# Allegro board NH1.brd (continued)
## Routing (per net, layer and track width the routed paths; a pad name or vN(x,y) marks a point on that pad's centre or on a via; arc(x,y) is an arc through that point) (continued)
DDI0_HDMI_SDA_ALS: length 22.3
  IN1 w0.381: v1(13.51,88.04) 15,89.53 21.32,89.53 21.93,88.91 21.93,86.07 23.86,84.14 25.73,84.14 26.78,83.09 v1(26.78,82.12)
  BOTTOM w0.102: R56.1 26.7,82.21 v1(26.78,82.12)
  BOTTOM w0.457: v1(13.51,88.04) 13.75,88.28 J1HDMI1.16
DDI0_HPD_N: length 68.1
  TOP w0.102: v1(8.75,53.47) 8.43,53.16 U1.E14
  IN1 w0.102: v1(8.75,53.47) 8.75,53.62 9.09,53.96 9.09,54.99 8.94,55.14 8.41,55.14 8.33,55.06 4.69,55.06 3.41,56.34 2.7,56.34 1.89,57.16 1.89,69.83 2.4,70.34 2.4,73.07 1.97,73.49 1.97,80.21 8.08,86.31 18.3,86.31 19.39,85.22 20.61,85.22 v1(20.99,84.84)
  BOTTOM w0.102: v1(20.99,84.84) 21.01,84.86 22.85,84.86 R1HDMI3.1 24.5,84.03 25.16,84.03 25.38,84.26 29.46,84.26 29.6,84.4 29.6,85.7 29.92,86.02 Q1HDMI2.3
DDI0_PLLOBS_DN: length 1.2
  TOP w0.102: v1(18.7,46.18) 19.03,46.51 U1.AA4
  BOTTOM w0.102: v1(18.7,46.18) 18.99,46.47 R1AS26.1
DDI0_PLLOBS_DP: length 1.2
  TOP w0.089: U1.AA3 v1(18.7,45.53)
  BOTTOM w0.102: R1AS26.2 18.86,45.69 v1(18.7,45.53)
DDI0_TX0_DN: length 56.2
  TOP w0.089: U1.AB3 v1(20.05,45.53)
  IN1 w0.117: v1(20.05,45.53) 20.12,45.6 20.57,45.6 21.07,45.1 21.48,45.1 21.93,45.55 22.29,45.55 22.69,45.15 23.15,45.15 23.71,45.71 24.01,45.71 24.47,45.25 25.18,45.25 25.71,45.78 25.71,46.51 25.97,46.78 26.64,46.78 27.66,47.79 27.66,48.25 27.47,48.44 27.47,48.68 27.61,48.82 29.14,48.82 29.55,49.22 29.55,49.79 29.22,50.12 28.85,50.12 28.68,50.29 28.68,50.53 28.85,50.7 29.22,50.7 29.55,51.03 29.55,51.5 29.22,51.82 28.85,51.82 28.68,52 28.68,52.24 28.85,52.41 29.22,52.41 29.55,52.74 29.55,52.99 29.55,53.22 30.14,53.81 30.14,60.54 28.13,62.56 28.13,63.2 28.13,65.61 28.53,66.02 28.53,68.58 28.21,68.91 27.96,68.91 27.79,69.08 27.79,69.32 27.96,69.49 28.21,69.49 28.53,69.82 28.53,71.18 28.19,71.52 27.91,71.52 27.81,71.62 27.81,72.45 27.95,72.58 28.82,72.58 29.12,72.88 29.12,73.79 28.9,74.01 28.41,74.01 28.22,74.2 28.22,74.43 28.36,74.56 28.93,74.56 29.17,74.81 29.17,75.38 28.75,75.8 28.37,76.18 28.37,76.68 28.75,77.06 28.75,77.53 28.37,77.91 28.37,78.26 28.81,78.71 28.81,79.18 28.51,79.48 28.2,79.48 27.93,79.75 27.93,79.89 28.11,80.06 v1(28.89,80.06)
  BOTTOM w0.131: C1HDMI8.2 29.42,81.38 29.42,80.6 v1(28.89,80.06)
DDI0_TX0_DP: length 56.2
  TOP w0.102: U1.AB4 19.72,46.5 v1(20.05,46.18)
  IN1 w0.117: v1(20.05,46.18) 20.05,46.03 20.21,45.87 20.68,45.87 21.18,45.37 21.36,45.37 21.81,45.82 22.4,45.82 22.8,45.42 23.04,45.42 23.6,45.98 24.12,45.98 24.58,45.52 25.07,45.52 25.44,45.89 25.44,46.62 25.86,47.05 26.53,47.05 27.39,47.9 27.39,48.14 27.2,48.33 27.2,48.79 27.5,49.09 29.03,49.09 29.28,49.34 29.28,49.68 29.1,49.85 28.74,49.85 28.41,50.18 28.41,50.64 28.74,50.97 29.1,50.97 29.28,51.14 29.28,51.38 29.1,51.56 28.74,51.56 28.41,51.88 28.41,52.35 28.74,52.68 29.1,52.68 29.28,52.85 29.28,53.1 29.28,53.11 29.28,53.33 29.87,53.93 29.87,60.43 27.86,62.44 27.86,63.31 27.86,65.72 28.27,66.13 28.27,68.47 28.09,68.64 27.85,68.64 27.52,68.97 27.52,69.43 27.85,69.76 28.09,69.76 28.27,69.93 28.27,71.06 28.08,71.25 27.8,71.25 27.54,71.51 27.54,72.56 27.84,72.85 28.71,72.85 28.85,72.99 28.85,73.68 28.79,73.74 28.3,73.74 27.95,74.09 27.95,74.54 28.24,74.83 28.81,74.83 28.9,74.92 28.9,75.27 28.48,75.69 28.1,76.07 28.1,76.79 28.48,77.17 28.48,77.41 28.1,77.79 28.1,78.38 28.54,78.82 28.54,79.07 28.4,79.21 28.08,79.21 27.66,79.64 27.66,80 28,80.33 28.57,80.33 v1(28.89,80.66)
  BOTTOM w0.131: C1HDMI7.2 29.02,81.63 29.14,81.51 29.14,80.72 29.08,80.66 v1(28.89,80.66)
DDI0_TX1_DN: length 57.1
  TOP w0.102: U1.AA1 19.08,44.56 v1(19.4,44.23)
  TOP w0.131: v1(30.26,83.01) 30.34,83.09 31.2,83.09 31.53,83.42 31.53,83.64 C1HDMI6.2
  IN1 w0.102: 20.31,44.49 20.29,44.49 20.28,44.5 20.2,44.5 20.19,44.51 19.87,44.51 19.76,44.39 19.56,44.39 v1(19.4,44.23)
  IN1 w0.117: 20.31,44.49 20.5,44.49 20.67,44.32 20.67,44.01 21,43.68 21.46,43.68 21.61,43.82 21.79,44.01 21.79,44.32 21.96,44.49 22.26,44.49 22.64,44.12 23.2,44.12 23.58,44.49 23.77,44.49 23.93,44.34 23.93,43.88 24.19,43.62 24.81,43.62 25.2,44.01 25.2,44.32 25.38,44.49 26.08,44.49 26.42,44.83 26.42,45.4 26.66,45.64 27.23,45.64 27.63,46.04 27.63,46.61 27.87,46.85 28.44,46.85 28.84,47.25 28.84,47.82 29.08,48.06 29.65,48.06 30.31,48.72 30.31,49.22 30.31,52.9 30.91,53.5 30.91,60.86 28.89,62.87 28.89,63.08 29.25,63.44 29.25,63.85 28.89,64.2 28.89,64.43 29.06,64.6 29.51,64.6 29.88,64.97 29.88,66.02 29.3,66.6 29.3,70.39 30.28,71.37 30.28,75.35 29.52,76.12 29.52,78.33 29.98,78.78 29.98,80.54 29.56,80.96 29.56,82.65 30,83.09 30.19,83.09 v1(30.26,83.01)
DDI0_TX1_DP: length 57.1
  TOP w0.102: v1(19.4,44.88) 19.64,44.88 19.72,44.96 U1.AB2
  TOP w0.131: C1HDMI5.2 31.08,83.92 31.25,83.75 31.25,83.53 31.08,83.37 30.43,83.37 v1(30.26,83.54)
  IN1 w0.102: 20.31,44.76 20.2,44.76 20.2,44.76 19.77,44.76 19.65,44.64 19.48,44.64 19.4,44.72 v1(19.4,44.88)
  IN1 w0.117: v1(30.26,83.54) 30.08,83.36 29.89,83.36 29.29,82.76 29.29,80.85 29.71,80.42 29.71,78.9 29.25,78.44 29.25,76 30.01,75.24 30.01,71.48 29.03,70.5 29.03,66.49 29.61,65.91 29.61,65.08 29.4,64.87 28.95,64.87 28.62,64.54 28.62,64.09 28.98,63.73 28.98,63.55 28.62,63.19 28.62,62.76 30.64,60.75 30.64,53.61 30.04,53.01 30.04,52.79 30.04,52.79 30.04,48.83 29.53,48.33 28.97,48.33 28.57,47.93 28.57,47.36 28.33,47.12 27.76,47.12 27.36,46.72 27.36,46.15 27.12,45.91 26.55,45.91 26.15,45.51 26.15,44.94 25.97,44.76 25.26,44.76 24.94,44.43 24.94,44.12 24.7,43.89 24.3,43.89 24.2,43.99 24.2,44.45 23.89,44.76 23.47,44.76 23.09,44.39 22.75,44.39 22.38,44.76 21.85,44.76 21.52,44.43 21.52,44.12 21.35,43.95 21.11,43.95 20.94,44.12 20.94,44.43 20.61,44.76 20.31,44.76
DDI0_TX2_DN: length 59.7
  TOP w0.089: U1.Y1 18.38,44.55 v1(18.06,44.23)
  TOP w0.131: C1HDMI4.2 31.48,86.56 31.62,86.56 v1(31.77,86.71)
  IN1 w0.102: v1(18.06,44.23) 18.19,44.23 19.11,43.32 19.11,43.3 19.12,43.29
  IN1 w0.117: 19.12,43.29 19.55,42.87 21.73,42.87 22.22,43.35 22.62,43.35 23.25,42.71 25.39,42.71 31.08,48.41 31.08,52.58 31.67,53.18 31.67,61.2 30.07,62.8 30.07,64.08 30.65,64.65 30.65,66.34 30.07,66.91 30.07,70.07 31.05,71.05 31.05,75.67 30.29,76.43 30.29,78.01 30.74,78.47 30.74,80.85 30.32,81.28 30.32,82.06 31.46,83.19 31.46,84.19 32.43,85.16 32.43,86.36 32.17,86.62 31.86,86.62 v1(31.77,86.71)
DDI0_TX2_DP: length 59.7
  TOP w0.089: v1(18.06,44.88) 18.38,45.2 U1.Y2
  TOP w0.131: C1HDMI3.2 31.18,86.15 31.31,86.27 31.66,86.27 31.77,86.17 v1(31.77,86.02)
  IN1 w0.102: 19.31,43.48 19.3,43.49 19.29,43.49 18.06,44.72 v1(18.06,44.88)
  IN1 w0.117: 19.31,43.48 19.66,43.13 21.62,43.13 22.11,43.62 22.73,43.62 23.36,42.98 25.28,42.98 30.81,48.52 30.81,52.7 31.4,53.29 31.4,61.09 29.8,62.69 29.8,64.19 30.38,64.76 30.38,66.22 29.8,66.8 29.8,70.18 30.78,71.16 30.78,75.56 30.02,76.32 30.02,78.12 30.48,78.58 30.48,80.74 30.05,81.16 30.05,82.17 31.19,83.3 31.19,84.31 32.16,85.27 32.16,86.25 32.06,86.35 31.89,86.35 31.77,86.23 v1(31.77,86.02)
DDI0_TX3_DN: length 67.7
  TOP w0.089: U1.Y3 18.38,45.85 v1(18.06,45.53)
  TOP w0.131: C1HDMI2.2 31.49,88.72 31.78,88.72 v1(31.83,88.76)
  IN1 w0.102: 22.77,46.59 22.73,46.59 22.58,46.74 20.32,46.74 20.29,46.77 18.94,46.77 18.63,47.08 17.41,47.08 16.85,46.53 16.85,45.86 17.18,45.53 v1(18.06,45.53)
  IN1 w0.117: v1(31.83,88.76) 31.73,88.67 30.99,88.67 30.59,88.26 30.59,87.64 30.42,87.47 30.17,87.47 30,87.64 30,88.26 29.67,88.59 29.11,88.59 28.61,88.09 28.61,86.45 28.94,86.12 30.51,86.12 30.68,85.95 30.68,85.71 30.51,85.54 28.94,85.54 28.61,85.21 28.61,84.18 27.78,83.35 27.78,81.98 26.82,81.02 26.82,68.46 27.4,67.87 27.4,66.85 27.22,66.66 27.22,63.52 27.22,62.12 29.23,60.1 29.23,54.21 27.56,52.54 27.56,50.62 26.08,49.14 26.08,48.6 26.49,48.19 26.49,47.95 26.31,47.78 26.07,47.78 25.49,48.36 25.03,48.36 24.58,47.91 24.58,47.44 24.85,47.17 24.85,46.92 24.68,46.75 24.44,46.75 24.16,47.03 23.7,47.03 23.26,46.59 22.77,46.59
DDI0_TX3_DP: length 67.6
  TOP w0.089: v1(18.06,46.18) 18.38,46.5 U1.Y4
  TOP w0.131: C1HDMI1.2 31.2,88.31 31.32,88.43 31.64,88.43 31.83,88.24 v1(31.83,88.19)
  IN1 w0.102: 22.77,46.32 22.64,46.32 22.47,46.49 20.21,46.49 20.19,46.51 18.84,46.51 18.52,46.83 17.51,46.83 17.11,46.42 17.11,45.97 17.29,45.79 17.85,45.79 18.06,46 v1(18.06,46.18)
  IN1 w0.117: v1(31.83,88.19) 31.83,88.27 31.7,88.4 31.11,88.4 30.86,88.15 30.86,87.53 30.53,87.2 30.06,87.2 29.73,87.53 29.73,88.15 29.56,88.32 29.22,88.32 28.88,87.98 28.88,86.56 29.05,86.39 30.62,86.39 30.95,86.06 30.95,85.59 30.62,85.27 29.05,85.27 28.88,85.1 28.88,84.07 28.05,83.24 28.05,81.87 27.09,80.9 27.09,68.57 27.67,67.99 27.67,66.74 27.49,66.55 27.49,63.41 27.49,62.23 29.5,60.22 29.5,54.1 27.83,52.43 27.83,50.51 26.35,49.03 26.35,48.71 26.76,48.31 26.76,47.84 26.43,47.51 25.96,47.51 25.38,48.09 25.14,48.09 24.85,47.79 24.85,47.55 25.12,47.28 25.12,46.81 24.79,46.48 24.32,46.48 24.05,46.76 23.81,46.76 23.38,46.32 22.77,46.32
DDR3_DRAM_PWROK: length 74.1
  TOP w0.102: v1(10.17,29.85) 10.05,29.73 U1AP1.11 ; R1AS12.2 25.89,56.62 25.37,56.62 25.09,56.34 23.37,56.34 22.86,56.86 v1(22.77,56.86) 22.42,56.86 22.39,56.82 20.74,56.82 20.45,57.11 U1.AC20
  IN1 w0.102: v1(28.97,24.01) 28.81,24.16 28.81,28.76 27.24,30.33 17.06,30.33 16.18,29.45 16.18,26.33 15.89,26.04 13.73,26.04 13.29,26.47 13.29,28.04 11.74,29.6 10.42,29.6 v1(10.17,29.85)
  IN2 w0.102: v1(22.77,56.86) 24.3,55.33 25.82,55.33 26.41,54.73 26.41,54.73 28.71,52.43 28.71,41.15 29.42,40.44 29.42,24.47 v1(28.97,24.01)
DDR3_SOC_CMDPU: length 3.6
  TOP w0.254: R1AS64.2 22.89,58.77 21.89,57.78 U1.AE21
DDR3_SOC_DQTPU: length 3.3
  TOP w0.254: U1.AE20 22.19,57.11 22.6,57.52 R1AS73.2
DDR3_SOC_ODTPU: length 6.7
  TOP w0.254: R1AS63.2 25.54,61.91 25.54,61.2 25.03,60.69 24.51,60.69 24.12,60.29 24.12,59.93 23.42,59.23 22.84,59.23 22.06,58.45 U1.AE22
DDR3_VCCA_PWROK: length 73
  TOP w0.102: v2(25.14,55.94) 24.95,55.75 R1AS36.2 24.1,55.33 22.94,56.48 22.54,56.48 22.4,56.62 20.65,56.62 20.49,56.78 20.05,56.78 U1.AB20 ; v1(10.17,29.19) 10.03,29.33 U1AP1.12
  IN1 w0.102: v1(10.17,29.19) 10.4,29.42 11.66,29.42 13.12,27.97 13.12,26.4 13.65,25.86 15.96,25.86 16.36,26.26 16.36,29.38 17.13,30.15 27.17,30.15 28.64,28.68 28.64,23.7 v1(28.86,23.47)
  IN2 w0.102: v1(28.86,23.47) 28.94,23.47 29.42,23.96 29.42,24.18 29.63,24.38 29.63,40.54 28.92,41.25 28.92,52.51 28.76,52.67 28.76,52.67 25.5,55.94 v2(25.14,55.94)
DDR3_VREF: length 8.9
  TOP w0.165: 22.63,58.01 22.06,57.43 21.45,57.43 21.12,57.11 U1.AD20
  TOP w0.254: 22.63,58.01 22.77,58.15 27.13,58.15 R1AS77.1 C1AS71.2 R1AS76.2
DDR3L_ZQ_L8_A: length 4
  TOP w0.14: v1(2.96,75.96) 3.85,75.96 4.26,76.36 U1AM1.L8
  BOTTOM w0.102: R1AM1.1 2.96,76.06 v1(2.96,75.96)
DDR3L_ZQ_L8_B: length 3.5
  BOTTOM w0.14: R1AM2.1 12.37,75.95 9.94,75.95 9.52,76.37 9.31,76.37 U1AM2.L8
DDR3L_ZQ_L8_C: length 6.2
  TOP w0.102: U1AM3.L8 19.55,76.36
  TOP w0.14: v1(17.71,75.04) 17.71,75.74 18.04,76.06 18.47,76.06 18.52,76.01 19.19,76.01 19.55,76.36
  BOTTOM w0.102: v1(17.71,75.04) 17.71,75.65 16.3,77.06 R1AM3.1
DDR3L_ZQ_L8_D: length 4.2
  BOTTOM w0.102: U1AM4.L8 24.81,76.36 25.2,75.98
  BOTTOM w0.14: R1AM4.1 27.64,76.56 26.23,76.56 25.65,75.98 25.2,75.98
DLD01: length 4.8
  TOP w0.203: 10.17,24.67 10.55,25.05 U1AP1.21
  TOP w0.381: 10.17,24.67 9.19,24.67 8.75,24.23 8.75,23.82 7.91,22.98 C1AP24.1
DLDO4: length 1.8
  TOP w0.203: U1AP1.17 v1(8.24,27.33)
  BOTTOM w0.457: C1AP27.1 7.75,27.33 v1(8.24,27.33)
ELDO2: length 4.6
  TOP w0.203: U1AP1.2 8.72,33.33 8.37,33.69 8.37,34.09 8.32,34.13
  TOP w0.381: 8.32,34.13 8.32,34.7 7.9,35.13 7.9,35.14 6.64,36.4 C1AP29.1
EMMC_CLK: length 13.1
  TOP w0.102: v1(22,48.84) 21.68,49.16 U1.AE8
  IN1 w0.102: v1(22,48.84) 22.15,48.84 24.6,51.28 24.6,51.62 25.34,52.36 26.19,52.36 27.27,53.45 27.27,56.42 26.73,56.96 v1(26.73,57.66)
  BOTTOM w0.14: v1(26.73,57.66) 26.66,57.66 26.18,58.14 U1EMMC1.M6
EMMC_CMD: length 14.9
  TOP w0.102: U1.AB8 19.73,49.16 v1(20.05,48.84)
  IN1 w0.102: v1(20.05,48.84) 20.38,49.17 20.38,50.03 20.37,50.04 20.37,50.31 20.56,50.51 20.57,50.51 20.87,50.81 22.14,50.81 22.96,51.62 23.29,51.62 23.63,51.96 23.63,52.32 24.69,53.37 24.69,57.82 25.04,58.17 25.6,58.17 v1(26.16,57.61)
  BOTTOM w0.14: U1EMMC1.M5 25.63,58.14 v1(26.16,57.61)
EMMC_DATA_0: length 9.6
  TOP w0.102: v1(20.05,48.18) 19.73,48.5 U1.AB7
  IN1 w0.102: v1(25.29,51.42) 25.5,51.21 25.5,50.55 25.13,50.18 24.85,50.18 22.68,48 22.64,48 22.64,48 22.53,48 22.38,47.85 20.38,47.85 v1(20.05,48.18)
  BOTTOM w0.102: U1EMMC1.A3 24.62,52.09 v1(25.29,51.42)
EMMC_DATA_1: length 8.5
  TOP w0.102: v1(20.7,48.18) 20.38,48.5 U1.AC7
  IN1 w0.102: v1(20.7,48.18) 20.77,48.25 22.49,48.25 24.95,50.7 v1(25.14,50.7)
  BOTTOM w0.102: U1EMMC1.A4 25.12,52.38 25.11,52.37 25.11,52.15 25.69,51.57 25.69,51.52
  BOTTOM w0.14: v1(25.14,50.7) 25.4,50.7 25.64,50.95 25.64,51.23 25.69,51.28 25.69,51.52
EMMC_DATA_2: length 9.1
  TOP w0.102: v1(20.7,48.84) 20.38,49.16 U1.AC8
  IN1 w0.102: v1(26.35,51.67) 26.27,51.75 25.16,51.75 24.9,51.49 24.9,51.16 22.89,49.15 22.88,49.15 22.23,48.51 21.16,48.51 20.83,48.84 v1(20.7,48.84)
  BOTTOM w0.102: U1EMMC1.A5 25.62,52.42 26.35,51.69 v1(26.35,51.67)
EMMC_DATA_3: length 6.8
  TOP w0.102: U1.AB9 v1(20.05,49.48)
  IN1 w0.102: v1(20.05,49.48) 20.05,49.77 20.05,49.77 20.05,50.4 20.74,51.08 21.78,51.08 v1(22.77,52.08)
  BOTTOM w0.076: 23.2,52.89 23.87,52.89 U1EMMC1.B2
  BOTTOM w0.089: 22.77,52.43 22.77,52.46 23.2,52.89
  BOTTOM w0.14: 22.77,52.43 v1(22.77,52.08)
EMMC_DATA_4: length 8.1
  TOP w0.102: v1(19.4,49.48) 19.07,49.8 U1.AA9
  IN1 w0.102: v1(19.4,49.48) 19.8,49.88 19.8,50.55 20.6,51.35 21.58,51.35 22.63,52.41 23,52.41 v1(23.3,52.1)
  BOTTOM w0.076: U1EMMC1.B3 24.37,52.89 24.37,52.49
  BOTTOM w0.089: 24.37,52.49 23.99,52.1 v1(23.3,52.1)
EMMC_DATA_5: length 12.4
  TOP w0.102: v1(18.75,48.83) 18.75,48.83 U1.AA8
  IN1 w0.102: v1(18.75,48.83) 19.97,47.6 22.49,47.6 22.63,47.74 22.74,47.74 22.75,47.75 22.85,47.75 24.98,49.88 25.25,49.88 26.06,50.68 v1(26.06,51.11)
  BOTTOM w0.076: U1EMMC1.B4 25.38,52.89 25.38,52.26
  BOTTOM w0.089: 25.38,52.26 26,51.64 26,51.17 v1(26.06,51.11)
EMMC_DATA_6: length 15.7
  TOP w0.102: U1.Y8 v1(18.1,49.48)
  IN1 w0.102: v1(27.07,51.62) 27.07,51.17 26.67,50.76 26.67,50.43 25.51,49.27 25.23,49.27 23.06,47.09 19.76,47.09 19.01,47.84 18.57,47.84 18.1,48.32 v1(18.1,49.48)
  BOTTOM w0.076: U1EMMC1.B5 25.88,52.89 25.88,52.5
  BOTTOM w0.089: v1(27.07,51.62) 26.98,51.62 26.38,52.23 26.15,52.23 25.88,52.5
EMMC_DATA_7: length 13.3
  TOP w0.102: U1.Y7 18.42,48.46 v1(18.7,48.18)
  IN1 w0.102: v1(27.01,52.15) 26.93,52.15 26.73,51.95 26.73,51.26 26.36,50.89 26.36,50.55 25.38,49.57 25.11,49.57 22.93,47.39 22.64,47.39 22.59,47.34 19.87,47.34 19.03,48.18 v1(18.7,48.18)
  BOTTOM w0.076: U1EMMC1.B6 26.38,52.89 26.73,52.89 26.87,52.74 26.87,52.29
  BOTTOM w0.089: 26.87,52.29 v1(27.01,52.15)
EMMC_RESET: length 13.3
  TOP w0.102: v1(21.35,48.84) 21.03,49.16 U1.AD8
  IN1 w0.102: v1(21.35,48.84) 21.47,48.84 24.11,51.48 24.11,52.12 24.85,52.85 25.89,52.85 26.79,53.75 26.79,56.22 v1(25.4,57.61)
  BOTTOM w0.102: U1EMMC1.K5 25.62,57.38 v1(25.4,57.61)
GPIO_RCOMP: length 2.3
  TOP w0.254: R1AS49.1 4.07,46.92 4.33,46.66 4.34,46.66 4.6,46.41 5.48,46.41 5.58,46.51 U1.A4
HDA_RCOMP: length 3.8
  TOP w0.203: R1AS45.1 24.33,51.97 23.16,53.15 U1.AE14
HDMI_POWER_DN: length 2
  TOP w0.102: 28.29,89.21 v1(28.54,89.46)
  TOP w0.117: EU1HDMI1.12 28.29,89.21
  BOTTOM w0.102: v1(28.54,89.46) 28.1,89.9 R1HDMI1.2
HOLD_N_FLASH: length 5
  TOP w0.102: R1SPI4.1 27.93,51.5 27.93,51.94 28.59,52.61 29.53,52.61 29.84,52.29 EU1SPI1.7
I2C_4_PMIC_SCL: length 44.1
  TOP w0.102: U1AP1.51 19.25,31.33 19.45,31.53 22.9,31.53 v1(22.94,31.56) 23.43,32.05 TP24.1 24.17,32.82 24.17,33.24 24.37,33.44 24.37,36.82 25.12,37.57 25.81,37.57 R69.2 ; U1.AE16 21.68,54.46 v1(22,54.78)
  IN2 w0.102: v1(22.94,31.56) 22.94,34.35 22.01,35.29 22.01,39.71 21.45,40.27 21.45,43.28 21.45,43.28 21.45,43.43 21.46,43.45 21.46,46.21 20.51,47.16 18.47,47.16 18.12,47.52 18.12,48.15 18.12,48.98 17.75,49.35 17.75,51.32 17.74,51.33 17.74,51.6 17.75,51.61 17.75,52.43 17.63,52.55 17.63,53 17.75,53.12 17.75,53.58 17.77,53.6 17.77,53.61 18.67,54.51 19.96,54.51 20.57,55.12 21.65,55.12 v1(22,54.78)
I2C_4_PMIC_SDA: length 36.1
  TOP w0.102: U1.AD16 21.32,54.16 21.32,53.12 21.37,53.07 21.37,53.05 21.56,52.87 21.57,52.87 21.6,52.84 23.11,52.84 24.89,51.06 25.29,51.06 25.59,50.75 25.79,50.75 TP23.1 26.32,50.22 26.32,49.79 27.39,48.72 27.39,41.77 27.02,41.39 27.02,40.47 27.94,39.55 28.55,39.55 28.76,39.34 28.76,39.05 28.3,38.59 26.82,38.59 R68.2 25.34,38.08 24.17,36.9 24.17,33.52 22.37,31.73 U1AP1.52
I2S_1_BT_WWAN_CLK: length 64.3
  TOP w0.102: U1.AC13 20.05,52.15 v1(20.05,52.13)
  IN2 w0.102: v1(20.05,52.13) 20.73,52.81 22.41,52.81 22.77,52.46 23.51,52.46 23.68,52.28 23.68,51.14 25.97,48.86 25.97,40.65 27.04,39.58 27.04,26.12 26.02,25.11 26.02,23.17 23.53,20.68 20.15,20.68 19.31,19.84 17.43,19.84 14.62,17.02 v1(6.46,17.02)
  BOTTOM w0.102: U1WF1.16 4.45,12.95 6.46,14.97 v1(6.46,17.02)
I2S_1_BT_WWAN_FS: length 63.3
  TOP w0.102: v1(20.7,53.48) 20.7,53.47 U1.AC14
  IN2 w0.102: v1(6.06,16.31) 14.57,16.31 17.67,19.41 20.28,19.41 21.15,20.27 23.97,20.27 26.43,22.73 26.43,24.94 27.44,25.95 27.44,39.75 26.43,40.77 26.43,50.04 25.4,51.06 25.07,51.06 24.13,52 24.13,52.41 23.6,52.94 23.1,52.94 22.56,53.48 v1(20.7,53.48)
  BOTTOM w0.102: v1(6.06,16.31) 4.06,14.32 3.76,14.32 3.57,14.12 U1WF1.17
I2S_1_BT_WWAN_RXD: length 67.6
  TOP w0.102: U1.Y10 18.74,50.18 v1(18.75,50.18)
  IN2 w0.102: v1(18.75,50.18) 18.75,50.64 19.07,50.96 19.07,50.97 19.26,51.16 19.27,51.16 19.74,51.64 22.9,51.64 25.77,48.77 25.77,41.28 24.9,40.41 24.9,39.05 26.68,37.27 26.68,26.06 25.82,25.19 25.82,23.49 23.21,20.88 20.07,20.88 19.26,20.07 17.33,20.07 14.53,17.28 7.38,17.28 v1(7.27,17.38)
  BOTTOM w0.102: U1WF1.14 3.95,10.61 4.58,11.25 5.84,11.25 7.27,12.68 v1(7.27,17.38)
I2S_1_BT_WWAN_TXD: length 66.2
  TOP w0.102: v1(20.05,53.48) 20.05,53.47 U1.AB14
  IN2 w0.102: v1(20.05,53.48) 20.39,53.14 22.51,53.14 23,52.66 23.59,52.66 23.89,52.36 23.89,51.23 26.22,48.89 26.22,40.68 27.24,39.67 27.24,26.04 26.22,25.02 26.22,22.81 23.89,20.48 21.06,20.48 20.2,19.61 17.59,19.61 14.64,16.67 v1(6.87,16.67)
  BOTTOM w0.102: v1(6.87,16.67) 6.87,13.34 5.31,11.78 U1WF1.15
ICLK_ICOMP: length 1.2
  TOP w0.254: v1(16.75,44.23) 17.07,44.55 U1.V1
  BOTTOM w0.254: v1(16.75,44.23) 16.14,44.23 R1AS51.1
M0_BS0: length 63
  TOP w0.102: U1.M21 v1(13.4,58.12)
  TOP w0.112: 7.73,77.37 7.2,77.37
  TOP w0.14: U1AM3.M2 24.55,76.93 24.43,76.81 24.28,76.81 24.14,76.95 24.14,77.37 23.96,77.55 23.3,77.55 23.12,77.37 v1(22.65,77.37) ; 7.73,77.37 7.96,77.37 8.16,77.58 8.89,77.58 9.31,77.16 U1AM1.M2 ; 7.2,77.37 v1(6.65,77.37)
  IN1 w0.102: v1(13.4,58.12) 13.12,58.12 13.01,58.22 13.01,58.78 12.8,58.99 12.8,60.43 12.53,60.7 12.53,63.04 13.4,63.91 13.4,64.8 13.94,65.35 13.94,65.6 14.02,65.68 14.17,65.68 14.3,65.8 14.3,65.93 14.21,66.02 14.02,66.02 13.93,66.11 13.93,66.23 14.02,66.32 14.21,66.32 14.3,66.41 14.3,66.54 14.21,66.63 14.02,66.63 13.93,66.72 13.93,66.84 14.02,66.93 14.21,66.93 14.3,67.02 14.3,67.15 14.21,67.24 14.02,67.24 13.93,67.33 13.93,67.45 14.02,67.54 14.21,67.54 14.3,67.63 14.3,67.76 14.21,67.85 14.02,67.85 13.93,67.94 13.93,68.06 14.02,68.15 14.21,68.15 14.3,68.24 14.3,68.37 14.21,68.46 14.02,68.46 13.93,68.55 13.93,68.75 14.03,68.85 14.4,68.85 14.5,68.95 14.5,72.13 13.59,73.04 13.59,75.63 13.4,75.82 13.4,79.41 13.22,79.58 12.79,79.58 v1(12.42,79.21)
  IN2 w0.102: v1(6.65,77.37) 6.09,77.37 4.96,78.5 4.79,78.5 4.69,78.4 4.69,78.18 5.85,77.02 6.84,77.02 7.2,77.37 8.95,77.37 10.79,79.21 v1(12.42,79.21) 14.66,79.21 15,78.87 15.13,78.87 15.22,78.78 15.22,78.4 15.3,78.31 15.43,78.31 15.52,78.4 15.52,78.78 15.61,78.87 17.75,78.87 18.22,78.41 18.57,78.41 18.76,78.59 20,78.59 21.22,77.37 v1(22.65,77.37)
  BOTTOM w0.112: 21.65,77.37 22.21,77.37
  BOTTOM w0.14: v1(6.65,77.37) 6.18,77.37 6,77.55 5.19,77.55 5.02,77.73 4.78,77.73 4.51,77.45 U1AM2.M2 ; 22.21,77.37 v1(22.65,77.37) ; 21.65,77.37 20.89,77.37 20.71,77.55 20.14,77.55 U1AM4.M2
M0_BS1: length 65.1
  TOP w0.102: U1.N19 v1(13.42,56.12) ; 21.6,79.51 v1(22.65,79.51)
  TOP w0.14: U1AM3.N8 20.15,78.37 20.15,78.88 20.43,79.17 21.26,79.17 21.6,79.51 ; v1(6.65,79.51) 5.93,79.51 5.55,79.13 5.16,79.13 4.91,78.88 4.91,78.37 U1AM1.N8
  IN1 w0.102: v1(13.42,56.12) 13.04,56.5 12.89,56.5 11.59,57.8 10.59,57.8 10.37,58.02 9.76,59.92 9.76,63.91 10.02,64.83 10.2,65.46 10.2,67.37 10.89,68.44 11.47,69.02 11.47,75.16 11.31,75.32 11.31,75.93 11.63,77.6 11.63,80.24 v1(12.35,81.68) 11.59,81.68 11.5,81.59 11.5,81.32 11.41,81.23 11.28,81.23 11.19,81.32 11.19,81.59 11.1,81.68 10.84,81.68 10.23,81.07 10.23,80.94 10.83,80.34 10.83,80.22 10.74,80.13 10.61,80.13 10.02,80.73 9.89,80.73 9.8,80.64 9.8,80.51 10.4,79.91 10.4,79.79 10.12,79.51 v1(6.65,79.51)
  IN2 w0.102: v1(12.35,81.68) 12.54,81.49 13.22,81.49 13.52,81.79 14.79,82.04 15.5,82.04 15.57,81.98 19.2,81.98 21.68,79.51 v1(22.65,79.51)
  BOTTOM w0.102: 7.71,79.51 v1(6.65,79.51)
  BOTTOM w0.14: U1AM2.N8 9.31,77.96 8.9,78.37 8.9,78.91 8.65,79.17 8.05,79.17 7.71,79.51 ; U1AM4.N8 24.55,77.68 24.45,77.59 24.25,77.59 24.11,77.73 24.11,78.95 23.91,79.15 23.57,79.15 23.47,79.26 23.18,79.26 22.93,79.51 v1(22.65,79.51)
M0_BS2: length 63.6
  TOP w0.102: U1.K22 12,58.45 12.1,58.55 12.1,59.34 12.3,59.54 12.3,60.85 12.11,61.04 ; 23.22,77.02 v1(21.89,77.02)
  TOP w0.14: v1(15.01,77.99) 15.34,77.66 15.34,77.46 13.96,76.08 13.96,73.02 14.49,72.48 14.49,64.98 14.39,64.88 14.23,64.88 14.13,64.98 13.97,64.98 13.85,64.86 13.85,64.73 14.36,64.22 14.36,64.09 14.26,63.98 14.06,63.98 13.62,64.43 13.42,64.43 12.11,63.12 12.11,62.76 12.32,62.55 12.32,62.35 12.11,62.14 12.11,61.04 ; v1(7.41,77.02) 7.41,76.83 7.55,76.69 7.83,76.69 8.31,77.16 U1AM1.M3 ; U1AM3.M3 23.47,77.16 23.37,77.16 23.22,77.02
  IN2 w0.102: v1(21.89,77.02) 21.84,76.97 20.29,76.97 20.18,77.08 20.18,77.22 20.28,77.32 20.58,77.32 20.65,77.39 20.65,77.51 20.54,77.63 20.4,77.63 20.31,77.72 20.31,77.84 20.22,77.93 20.09,77.93 20.01,77.84 20.01,77.57 19.92,77.48 19.79,77.48 19.7,77.57 19.7,78.16 19.61,78.25 19.48,78.25 19.4,78.16 19.4,77.54 19.31,77.45 19.18,77.45 19.09,77.54 19.09,78.15 19,78.24 18.88,78.24 18.79,78.15 18.79,77.54 18.68,77.44 17.98,77.44 17.84,77.58 17.84,78.35 17.64,78.55 17.4,78.55 17.31,78.46 17.31,77.66 17.2,77.55 17.07,77.55 16.96,77.66 16.96,78.46 16.87,78.55 16.56,78.55 16.48,78.46 16.48,78.2 16.39,78.11 16.26,78.11 16.17,78.2 16.17,78.46 16.08,78.55 15.95,78.55 15.87,78.46 15.87,77.58 15.75,77.47 15.61,77.47 15.5,77.58 15.5,77.89 15.4,77.99 v1(15.01,77.99) 14.58,77.99 14.49,78.09 14.49,78.78 14.38,78.88 14.24,78.88 14.15,78.79 14.15,77.54 14.06,77.45 13.94,77.45 13.85,77.54 13.85,78.79 13.76,78.88 13.63,78.88 13.54,78.79 13.54,77.84 13.45,77.75 13.33,77.75 13.24,77.84 13.24,78.69 13.11,78.82 12.92,78.82 12.8,78.71 12.8,78.48 12.71,78.39 12.59,78.39 12.5,78.48 12.5,78.71 12.4,78.81 12.25,78.81 12.15,78.71 12.15,77.88 12.05,77.78 11.91,77.78 11.82,77.87 11.82,78.5 11.72,78.6 11.58,78.6 11.48,78.5 11.48,78.34 11.36,78.22 10.23,78.22 9.03,77.02 v1(7.41,77.02)
  BOTTOM w0.102: 6.28,77.02 v1(7.41,77.02)
  BOTTOM w0.14: v1(21.89,77.02) 21.64,76.76 20.69,76.76 20.55,76.9 U1AM4.M3 ; U1AM2.M3 5.83,77.16 5.97,77.02 6.28,77.02
M0_CASB: length 59.2
  TOP w0.102: v1(14.1,56.82) 14.42,57.14 U1.P20
  TOP w0.14: U1AM3.K3 23.39,75.2 23.39,74.56 22.77,73.95 v1(22.65,73.95) ; v1(6.65,73.99) 6.96,74.29 7.6,74.29 8.04,74.72 8.04,74.81 8.51,75.28 U1AM1.K3
  IN1 w0.102: v1(15.76,73.57) 16.29,73.57 16.43,73.43 16.43,70.81 16.85,70.39 16.85,67.85 17.03,67.67 17.03,66.25 16.94,66.16 16.43,66.16 16.34,66.07 16.34,65.95 16.43,65.86 16.94,65.86 17.03,65.77 17.03,65.64 16.94,65.55 16.43,65.55 16.34,65.46 16.34,65.34 16.43,65.25 16.94,65.25 17.03,65.16 17.03,65.03 16.94,64.94 16.43,64.94 16.34,64.86 16.34,64.73 16.43,64.64 16.94,64.64 17.03,64.55 17.03,64.42 16.94,64.33 16.43,64.33 16.34,64.25 16.34,64.12 16.43,64.03 16.94,64.03 17.03,63.94 17.03,63.4 16.6,62.97 15.05,62.97 14.46,62.39 14.46,61.4 14.21,61.14 14.21,60.58 14.46,60.33 14.46,59.06 14.41,59.01 14.41,57.61 14.32,57.52 13.89,57.52 13.8,57.43 13.8,57.31 13.89,57.22 14.31,57.22 14.41,57.12 14.41,57.03 14.62,56.82 14.89,56.82 15,56.72 15,56.55 14.92,56.47 13.85,56.47 13.75,56.57 13.75,56.72 13.85,56.82 v1(14.1,56.82)
  IN2 w0.102: v1(6.65,73.99) 6.83,73.99 7.26,73.55 9.88,73.55 10.63,74.3 13.65,74.3 14.64,73.31 15.5,73.31 v1(15.76,73.57) 15.76,73.89 15.86,74 16.16,74 16.25,73.91 16.25,73.63 16.34,73.54 16.47,73.54 16.56,73.63 16.56,73.91 16.65,74 18.4,74 19.21,73.18 19.48,73.18 19.74,72.92 20.21,72.92 20.91,73.61 22.05,73.61 22.13,73.69 22.39,73.69 22.69,73.39 23.05,73.39 23.22,73.56 23.22,73.85 23.12,73.95 v1(22.65,73.95)
  BOTTOM w0.112: 21.69,75.05 22.07,75.05
  BOTTOM w0.14: 22.07,75.05 22.24,74.88 22.24,74.37 v1(22.65,73.95) ; U1AM4.K3 20.74,75.56 21.18,75.56 21.69,75.05 ; U1AM2.K3 5.6,75.27 5.6,75.26 5.8,75.06 5.8,74.47 6.29,73.99 v1(6.65,73.99)
M0_CKE0: length 70.9
  TOP w0.102: 21.71,75.05 22.33,75.05
  TOP w0.14: U1AM3.K9 19.24,75.56 19.64,75.96 20.81,75.96 21.71,75.05 ; v1(12.04,75.29) 12.04,77.03 11.9,77.17 11.7,77.17 11.54,77.01 11.54,75.09 12.13,74.5 12.13,74.26 12.03,74.16 11.57,74.16 11.47,74.06 11.47,73.91 11.57,73.81 12.03,73.81 12.13,73.71 12.13,73.28 11.24,72.4 11.24,70.77 11.16,70.69 11.16,65.63 11.06,65.53 10.6,65.53 10.5,65.43 10.5,65.29 10.6,65.19 11.06,65.19 11.16,65.09 11.16,64.85 11.01,64.7 10.35,64.7 10.09,64.44 10.09,59.92 9.46,59.29 9.46,58.77 U1.G22 ; 22.33,75.05 v1(22.62,74.77) ; v1(6.65,74.7) 6.65,74.87 5.55,75.97 4.32,75.97 3.91,75.56 U1AM1.K9
  IN2 w0.102: v1(6.65,74.7) 6.38,74.7 6.13,74.95 6.13,75.44 6.03,75.54 5.42,75.54 5.32,75.44 5.32,74.68 5.41,74.59 5.71,74.59 5.8,74.5 5.8,74.38 5.71,74.29 5.56,74.29 5.47,74.2 5.47,74.07 5.56,73.98 5.71,73.98 5.8,73.89 5.8,73.77 5.71,73.68 5.41,73.68 5.32,73.59 5.32,73.26 5.42,73.16 6.15,73.16 6.25,73.26 6.25,74.21 6.38,74.34 7,74.34 7.07,74.27 7.78,74.27 7.86,74.2 9.62,74.2 11.07,75.65 11.68,75.65 v1(12.04,75.29) 12.4,74.94 13.88,74.94 14.13,74.68 17.87,74.68 18.21,75.02 18.7,75.02 18.83,74.88 18.83,74.43 19.16,74.1 19.91,74.1 20,74.01 20.37,74.01 20.7,74.34 23.44,74.34 23.6,74.49 23.6,74.64 23.47,74.77 v1(22.62,74.77)
  BOTTOM w0.14: v1(6.65,74.7) 7.02,75.06 7.4,75.06 7.71,75.37 7.71,75.54 8.14,75.97 9.45,75.97 9.86,75.56 U1AM2.K9 ; R1AM13.2 13.59,75.52 12.27,75.52 v1(12.04,75.29) ; v1(22.62,74.77) 22.62,75.05 22.95,75.38 22.95,75.67 23.23,75.95 24.68,75.95 25.07,75.56 U1AM4.K9
M0_CLK0_DN: length 66.4
  TOP w0.102: U1.J22 v1(11.43,58.77)
  TOP w0.131: v1(22.24,73.29) 22.13,73.19 21.87,73.19 21.38,73.69 21.38,74.83 20.94,75.27 20.7,75.27 20.55,75.42 U1AM3.K7 ; U1AM1.K7 5.31,75.4 5.46,75.24 5.73,75.24 6.16,74.81 6.16,73.52 6.54,73.14 6.84,73.14 v1(7,73.29)
  IN1 w0.102: 10.63,59.76 10.65,59.76 10.69,59.79 10.91,59.79 11.1,59.61 11.1,59.11 v1(11.43,58.77)
  IN1 w0.117: v1(12.53,71.74) 12.33,71.55 12.12,71.55 11.85,71.27 11.85,68.52 11.75,68.43 11.5,68.43 11.25,68.18 11.25,67.82 11.5,67.57 12.16,67.57 12.3,67.43 12.3,67.18 12.19,67.06 10.96,67.06 10.67,66.78 10.67,66.36 10.92,66.1 11.99,66.1 12.09,66.01 12.09,65.88 11.99,65.78 10.87,65.78 10.62,65.53 10.62,65.18 10.87,64.93 11.99,64.93 12.09,64.83 12.09,64.7 11.99,64.61 10.54,64.61 10.29,64.35 10.29,63.82 10.54,63.57 11.15,63.57 11.25,63.48 11.25,63.34 11.15,63.25 10.54,63.25 10.29,63 10.29,62.64 10.54,62.39 11.21,62.39 11.3,62.3 11.3,62.16 11.21,62.07 10.54,62.07 10.29,61.82 10.29,61.46 10.54,61.21 11.21,61.21 11.3,61.12 11.3,60.99 11.21,60.89 10.42,60.89 10.17,60.64 10.17,60.03 10.44,59.76 10.63,59.76
  IN2 w0.117: v1(22.24,73.29) 22.12,73.18 21.19,73.18 20.22,72.2 19.35,72.2 19.03,72.53 19.03,72.68 18.18,73.53 17.17,73.53 15.2,71.56 12.72,71.56 v1(12.53,71.74) 12.36,71.57 12.14,71.57 12,71.71 12,72.01 12.31,72.33 13.18,72.33 13.5,72.64 13.5,73.16 13.19,73.46 11.84,73.46 11.11,72.73 10.34,72.73 10.03,72.42 10.03,72.06 9.88,71.9 8.68,71.9 8.52,72.06 8.52,72.7 8.05,73.17 7.12,73.17 v1(7,73.29)
  BOTTOM w0.131: R1AS55.1 13.44,71.51 12.76,71.51 v1(12.53,71.74) ; U1AM2.K7 8.51,75.42 8.38,75.29 8.16,75.29 7.86,74.99 7.86,73.53 7.47,73.14 7.15,73.14 v1(7,73.29) ; U1AM4.K7 23.75,75.37 23.63,75.25 23.36,75.25 23.07,74.96 23.07,73.67 22.55,73.14 22.39,73.14 v1(22.24,73.29)
M0_CLK0_DP: length 66.3
  TOP w0.102: U1.J23 v1(11.43,59.42)
  TOP w0.131: U1AM1.J7 5.31,74.86 5.45,75.01 5.63,75.01 5.92,74.72 5.92,73.42 6.44,72.9 6.85,72.9 v1(7.01,72.74) ; U1AM3.J7 20.55,74.88 20.7,75.03 20.84,75.03 21.14,74.73 21.14,73.59 21.83,72.9 22.09,72.9 v1(22.25,72.74)
  IN1 w0.102: v1(11.43,59.42) 11.3,59.55 11.3,59.69 11,59.99 10.69,59.99 10.65,60.03 10.63,60.03
  IN1 w0.117: 10.63,60.03 10.55,60.03 10.43,60.14 10.43,60.53 10.53,60.62 11.32,60.62 11.57,60.87 11.57,61.23 11.32,61.48 10.66,61.48 10.56,61.58 10.56,61.71 10.66,61.8 11.32,61.8 11.57,62.05 11.57,62.41 11.32,62.66 10.66,62.66 10.56,62.75 10.56,62.89 10.66,62.98 11.26,62.98 11.52,63.23 11.52,63.59 11.27,63.84 10.66,63.84 10.56,63.93 10.56,64.24 10.66,64.34 12.1,64.34 12.35,64.59 12.35,64.94 12.1,65.2 10.99,65.2 10.89,65.29 10.89,65.42 10.99,65.52 12.1,65.52 12.35,65.77 12.35,66.12 12.1,66.37 11.04,66.37 10.94,66.47 10.94,66.66 11.07,66.79 12.3,66.79 12.57,67.07 12.57,67.54 12.27,67.84 11.61,67.84 11.52,67.93 11.52,68.07 11.61,68.16 11.86,68.16 12.12,68.41 12.12,69.59 12.21,69.69 12.46,69.69 12.56,69.78 12.56,69.91 12.46,70.01 12.21,70.01 12.12,70.1 12.12,70.23 12.21,70.33 12.46,70.33 12.56,70.42 12.56,70.55 12.46,70.65 12.21,70.65 12.12,70.74 12.12,71.16 12.23,71.28 12.39,71.28 v1(12.53,71.14)
  IN2 w0.117: v1(22.25,72.74) 22.08,72.91 21.31,72.91 20.33,71.94 19.24,71.94 18.76,72.42 18.76,72.57 18.07,73.26 17.28,73.26 15.31,71.29 12.67,71.29 v1(12.53,71.14) 12.37,71.3 12.02,71.3 11.73,71.6 11.73,72.13 12.2,72.6 13.07,72.6 13.23,72.76 13.23,73.05 13.08,73.19 11.96,73.19 11.22,72.46 10.45,72.46 10.3,72.31 10.3,71.94 9.99,71.63 8.57,71.63 8.25,71.95 8.25,72.59 7.94,72.9 7.17,72.9 v1(7.01,72.74)
  BOTTOM w0.131: U1AM2.J7 8.51,74.93 8.38,75.06 8.26,75.06 8.09,74.89 8.09,73.43 7.57,72.9 7.18,72.9 v1(7.01,72.74) ; U1AM4.J7 23.75,74.91 23.64,75.02 23.46,75.02 23.31,74.86 23.31,73.57 22.65,72.91 22.42,72.91 v1(22.25,72.74) ; R1AS55.2 13.56,71.28 12.67,71.28 v1(12.53,71.14)
M0_CS0_B: length 67.4
  TOP w0.102: U1.P22 v1(14.74,58.77)
  TOP w0.14: U1AM3.L2 24.26,76.36 24.26,76.36 23.91,76.71 23.52,76.71 22.71,75.9 22.38,75.9 v1(21.89,75.41) ; U1AM1.L2 9.31,76.61 9.17,76.75 8.33,76.75 7.24,75.65 v1(7.24,75.45)
  IN1 w0.102: v1(14.74,58.77) 14.72,58.79 14.72,60.36 15.31,60.95 15.31,61.64 16.11,62.44 16.93,62.44 17.64,63.15 17.64,67.93 17.46,68.1 17.46,70.64 17.04,71.06 17.04,75.07 16.55,75.57 16.55,77.32 16.71,77.49 16.84,77.49 17,77.65 17,77.99 16.81,78.19 16.11,78.19 16.01,78.08 16.01,77.22 15.53,76.74 v1(15.53,75.8)
  IN2 w0.102: v1(7.24,75.45) 8.45,75.45 8.55,75.54 9.68,75.54 9.86,75.73 9.86,75.85 9.65,76.06 9.65,76.19 9.74,76.28 9.86,76.28 10.07,76.07 10.2,76.07 10.29,76.16 10.29,76.28 10.08,76.49 10.08,76.62 10.17,76.71 10.29,76.71 10.51,76.5 10.63,76.5 10.74,76.61 11.03,76.61 11.11,76.7 11.11,77.06 11.2,77.14 11.33,77.14 11.42,77.06 11.42,76.7 11.51,76.61 11.64,76.61 11.72,76.7 11.72,77.06 11.81,77.14 11.94,77.14 12.03,77.06 12.03,76.7 12.12,76.61 12.31,76.61 12.4,76.7 12.4,77 12.49,77.09 12.61,77.09 12.7,77 12.7,76.7 12.79,76.61 12.92,76.61 13.12,76.81 13.32,76.81 13.51,76.62 13.64,76.62 13.79,76.78 13.92,76.78 14.01,76.69 14.01,76.56 13.85,76.41 13.85,76.28 14.34,75.8 v1(15.53,75.8) 15.53,76.03 15.43,76.13 14.51,76.13 14.41,76.23 14.41,76.73 14.51,76.83 14.7,76.83 14.79,76.74 14.79,76.57 14.88,76.48 15.01,76.48 15.1,76.57 15.1,76.74 15.19,76.83 15.31,76.83 15.4,76.74 15.4,76.57 15.49,76.48 15.62,76.48 15.71,76.57 15.71,76.74 15.8,76.83 15.92,76.83 16.01,76.74 16.01,75.96 16.1,75.87 16.23,75.87 16.32,75.96 16.32,76.74 16.41,76.83 16.56,76.83 16.65,76.74 16.65,76.57 16.73,76.48 16.86,76.48 16.95,76.57 16.95,76.74 17.04,76.83 17.92,76.83 18.07,76.67 18.07,76.51 18.2,76.38 19.09,76.38 19.72,75.75 21.29,75.75 21.63,75.41 v1(21.89,75.41)
  BOTTOM w0.14: v1(21.89,75.41) 21.89,75.53 21.37,76.05 20.94,76.05 20.84,75.95 19.62,75.95 19.45,76.12 19.45,76.27 19.55,76.36 U1AM4.L2 ; v1(15.53,75.8) 14.56,76.77 R1AM20.2 ; U1AM2.L2 4.88,76.74 5.65,76.74 6.51,75.87 6.81,75.87 v1(7.24,75.45)
M0_DATA0: length 18.1
  TOP w0.102: U1.D18 v1(7.46,56.13)
  BOTTOM w0.102: 7.8,59.87 7.8,56.47 v1(7.46,56.13)
  BOTTOM w0.14: 7.8,59.87 7.8,60.45 10.45,63.1 10.45,64.85 10.86,65.26 10.86,66.88 10.7,67.04 10.55,67.04 10.45,67.14 10.45,67.28 10.55,67.38 10.83,67.38 10.93,67.48 10.93,67.62 10.83,67.72 10.55,67.72 10.45,67.82 10.45,67.96 10.55,68.06 10.83,68.06 10.93,68.16 10.93,68.92 10.3,69.55 9.72,69.55 U1AM2.C8
M0_DATA1: length 19.3
  TOP w0.112: U1.B18 v1(6.18,56.12)
  BOTTOM w0.14: v1(6.18,56.12) 6.18,56.9 5.79,57.29 5.79,58.43 5.94,58.58 5.94,61.1 6.05,61.21 6.19,61.21 6.51,60.9 6.65,60.9 6.75,61 6.75,61.14 6.44,61.46 6.44,61.6 6.54,61.7 6.68,61.7 6.99,61.38 7.14,61.38 7.24,61.49 7.24,61.63 6.92,61.94 6.92,62.08 7.02,62.19 7.16,62.19 7.48,61.87 7.62,61.87 7.72,61.97 7.72,62.11 7.41,62.43 7.41,62.57 7.51,62.67 7.65,62.67 7.96,62.35 8.11,62.35 8.21,62.46 8.21,62.6 7.89,62.91 7.89,63.05 7.99,63.16 8.13,63.16 8.45,62.84 8.59,62.84 8.69,62.94 8.69,63.08 8.38,63.4 8.38,63.54 8.51,63.67 8.51,67.8 U1AM2.A7
M0_DATA2: length 18.7
  TOP w0.102: U1.A21 5.7,57.91 4.48,57.91
  TOP w0.14: 4.48,57.91 v1(4.05,57.91)
  BOTTOM w0.14: v1(4.05,57.91) 4.05,58.62 3.86,58.8 3.86,58.8 3.63,59.04 3.63,61.68 6.28,64.33 6.28,64.58 6.18,64.68 5.55,64.68 5.45,64.78 5.45,64.93 5.55,65.03 6.18,65.03 6.28,65.13 6.28,65.27 6.18,65.37 5.55,65.37 5.45,65.47 5.45,65.61 5.55,65.71 6.18,65.71 6.28,65.81 6.28,65.95 6.18,66.06 5.55,66.06 5.45,66.16 5.45,66.3 5.55,66.4 6.18,66.4 6.28,66.5 6.28,66.72 6.14,66.86 5.5,66.86 5.31,67.05 U1AM2.A3
M0_DATA3: length 19.1
  TOP w0.102: U1.C18 v1(6.81,56.13)
  BOTTOM w0.102: v1(6.81,56.13) 7.14,56.46 7.14,59.87
  BOTTOM w0.14: U1AM2.B8 9.31,69.16 9.69,68.78 9.69,68.29 10.09,67.88 10.09,66.98 10.42,66.65 10.42,65.54 10.1,65.21 9.38,65.21 9.28,65.11 9.28,64.97 9.38,64.87 9.99,64.87 10.09,64.77 10.09,64.63 9.99,64.53 9.38,64.53 9.28,64.43 9.28,64.28 9.38,64.18 9.99,64.18 10.09,64.08 10.09,63.94 9.99,63.84 9.38,63.84 9.28,63.74 9.28,63.6 9.38,63.5 9.56,63.5 9.69,63.37 9.69,62.87 7.14,60.32 7.14,59.87
M0_DATA4: length 18.3
  TOP w0.102: U1.A22 4.48,58.45
  TOP w0.14: v1(3.49,58.65) 3.69,58.45 4.48,58.45
  BOTTOM w0.14: U1AM2.C2 4.51,69.96 4.91,69.55 4.91,64.86 4.81,64.76 4,64.76 3.9,64.66 3.9,64.51 4,64.41 4.81,64.41 4.91,64.31 4.91,64.17 4.81,64.07 4,64.07 3.9,63.97 3.9,63.83 4,63.73 4.81,63.73 4.91,63.63 4.91,63.45 3.21,61.75 3.21,58.92 v1(3.49,58.65)
M0_DATA5: length 18.9
  TOP w0.102: U1.B20 v1(6.16,57.43)
  BOTTOM w0.102: v1(6.16,57.43) 6.47,57.75 6.47,59.09
  BOTTOM w0.14: 6.47,59.09 6.47,60.22 9.05,62.79 9.05,63.25 8.93,63.38 8.93,65.49 9.03,65.59 9.33,65.59 9.43,65.69 9.43,65.83 9.33,65.93 9.03,65.93 8.93,66.03 8.93,66.17 9.03,66.27 9.71,66.27 9.81,66.37 9.81,66.51 9.71,66.61 9.03,66.61 8.93,66.72 8.93,66.86 9.03,66.96 9.64,66.96 9.74,67.06 9.74,67.2 9.64,67.3 9.03,67.3 8.93,67.4 8.93,70.34 U1AM2.D7
M0_DATA6: length 18.8
  TOP w0.102: 4.48,56.11 4.6,56 5.63,56 U1.A18
  TOP w0.14: 4.48,56.11 v1(4.3,56.29)
  BOTTOM w0.14: v1(4.3,56.29) 3.46,57.13 3.46,58.06 2.84,58.68 2.84,61.88 3.57,62.6 3.57,65 3.67,65.1 4.41,65.1 4.51,65.2 4.51,65.35 4.41,65.45 3.67,65.45 3.57,65.55 3.57,65.69 3.67,65.79 4.41,65.79 4.51,65.89 4.51,66.03 4.41,66.13 3.67,66.13 3.57,66.23 3.57,66.48 3.71,66.62 4.37,66.62 4.51,66.76 U1AM2.A2
M0_DATA7: length 18.2
  TOP w0.102: 4.48,58.77 6.15,58.77 U1.B22
  TOP w0.14: v1(4.03,59.17) 4.43,58.77 4.48,58.77
  BOTTOM w0.14: v1(4.03,59.17) 4.03,61.63 6.59,64.19 6.59,67.11 6.49,67.21 5.8,67.21 5.7,67.31 5.7,67.45 5.8,67.55 6.49,67.55 6.59,67.65 6.59,67.79 6.49,67.9 5.8,67.9 5.7,68 5.7,68.14 5.8,68.24 6.49,68.24 6.59,68.34 6.59,68.68 5.31,69.96 U1AM2.C3
M0_DATA8: length 22.1
  TOP w0.102: U1.C20 v1(6.81,57.43)
  IN1 w0.102: v1(4.91,74.36) 5.29,73.98 5.29,66.56 5.2,66.47 4.7,66.47 4.61,66.38 4.61,66.25 4.7,66.16 5.2,66.16 5.29,66.07 5.29,65.95 5.2,65.86 4.7,65.86 4.61,65.77 4.61,65.64 4.7,65.55 5.17,65.55 5.27,65.45 5.27,65.31 5.17,65.21 4.71,65.21 4.61,65.1 4.61,61.22 5.17,60.66 5.17,58.6 5.99,57.78 6.46,57.78 v1(6.81,57.43)
  BOTTOM w0.14: v1(4.91,74.36) 5.31,73.96 U1AM2.H3
M0_DATA9: length 19.4
  TOP w0.102: U1.D23 v1(7.47,59.42)
  IN1 w0.102: v1(7.35,70.6) 7.35,68.15 7.44,68.06 8.05,68.06 8.14,67.97 8.14,67.85 8.05,67.76 7.44,67.76 7.35,67.67 7.35,67.54 7.44,67.45 8.05,67.45 8.14,67.36 8.14,67.24 8.05,67.15 7.44,67.15 7.35,67.06 7.35,66.93 7.44,66.84 8.05,66.84 8.14,66.75 8.14,66.63 8.05,66.54 7.44,66.54 7.35,66.45 7.35,66.32 7.44,66.23 8.05,66.23 8.14,66.14 8.14,66.02 8.05,65.93 7.76,65.93 7.35,65.52 7.35,59.53 v1(7.47,59.42)
  BOTTOM w0.14: v1(7.35,70.6) 7.35,71.63 7.63,71.91 8.06,71.91 8.06,71.91 U1AM2.F7
M0_DATA10: length 20.5
  TOP w0.102: U1.E19 v1(8.76,56.78)
  IN1 w0.102: v1(8.76,56.78) 8.51,56.53 5.83,56.53 4.4,57.96 4.4,59.56 3.69,60.27 3.69,71.55 v1(4.11,71.96)
  BOTTOM w0.14: U1AM2.F2 v1(4.11,71.96)
M0_DATA11: length 19.1
  TOP w0.102: U1.E23 v1(8.13,59.43)
  IN1 w0.102: v1(10.83,73.09) 10.37,72.64 10.37,70.69 8.82,69.14 8.82,65.49 8.46,65.12 8.46,64.89 8.6,64.75 8.76,64.75 8.85,64.66 8.85,64.53 8.76,64.44 8.22,64.44 8.13,64.35 8.13,64.23 8.22,64.14 8.76,64.14 8.85,64.05 8.85,63.92 8.76,63.83 8.22,63.83 8.13,63.74 v1(8.13,59.43)
  BOTTOM w0.14: v1(10.83,73.09) 10.72,73.09 10.27,73.54 9.73,73.54 9.31,73.96 U1AM2.H8
M0_DATA12: length 20.3
  TOP w0.102: U1.D22 v1(7.47,58.77)
  IN1 w0.102: v1(10.84,73.89) 9.81,73.89 8.49,72.57 8.49,65.74 7.8,65.04 7.8,59.1 v1(7.47,58.77)
  BOTTOM w0.14: v1(10.84,73.89) 10.37,74.35 8.9,74.35 U1AM2.H7
M0_DATA13: length 20.7
  TOP w0.102: U1.E22 v1(8.13,58.78)
  IN1 w0.102: v1(8.13,58.78) 9.15,59.8 9.15,60.49 8.44,61.2 8.44,61.32 8.53,61.41 9.07,61.41 9.15,61.5 9.15,61.63 9.07,61.72 8.53,61.72 8.44,61.81 8.44,61.93 8.53,62.02 9.07,62.02 9.15,62.11 9.15,62.24 9.07,62.33 8.53,62.33 8.44,62.42 8.44,62.54 8.53,62.63 9.07,62.63 9.15,62.72 9.15,62.85 9.07,62.94 8.53,62.94 8.44,63.03 8.44,63.15 8.53,63.24 9.07,63.24 9.15,63.33 9.15,69.04 10.82,70.7 v1(10.82,71.49)
  BOTTOM w0.14: v1(10.82,71.49) 10.35,71.96 9.94,71.96 9.54,72.36 U1AM2.F8
M0_DATA14: length 21.8
  TOP w0.102: U1.E20 v1(8.13,57.44)
  IN1 w0.102: v1(8.13,57.44) 7.47,56.8 5.94,56.8 4.66,58.08 4.66,59.73 4,60.39 4,66.86 4.51,67.37 4.51,67.67 4,68.18 4,69.7 4.51,70.21 U1AM2.G2 v1(4.11,73.56)
  BOTTOM w0.14: v1(4.11,73.56) 4.51,73.16 U1AM2.G2
M0_DATA15: length 21.7
  TOP w0.102: U1.D20 v1(7.47,57.43)
  IN1 w0.102: v1(7.47,57.43) 7.09,57.07 6.05,57.07 4.91,58.2 4.91,60.53 4.8,60.65 4.65,60.65 4.53,60.53 4.4,60.53 4.31,60.62 4.31,60.75 4.43,60.86 4.43,61.02 4.3,61.14 4.3,66.73 4.43,66.86 4.88,66.86 4.98,66.96 4.98,67.26 4.81,67.43 4.81,67.57 4.98,67.74 4.98,68 4.82,68.16 4.45,68.16 4.36,68.25 4.36,68.38 4.45,68.47 4.89,68.47 4.98,68.56 4.98,68.68 4.89,68.77 4.39,68.77 4.3,68.86 4.3,68.99 4.39,69.08 4.89,69.08 4.98,69.16 4.98,69.29 4.89,69.38 4.45,69.38 4.36,69.47 4.36,69.6 4.45,69.69 4.82,69.69 4.91,69.77 v1(4.91,71.16)
  BOTTOM w0.14: U1AM2.E3 v1(4.91,71.16)
M0_DATA16: length 13.7
  TOP w0.14: U1AM1.A3 8.51,67.93 8.51,65.42 8.37,65.28 6.69,65.28 6.31,64.9 6.31,63.66 7.06,62.91 7.2,62.91 7.66,63.36 7.8,63.36 7.9,63.26 7.9,63.12 7.44,62.66 7.44,62.52 7.54,62.42 7.69,62.42 8.14,62.88 8.28,62.88 8.38,62.78 8.38,62.63 7.93,62.18 7.93,62.04 8.52,61.45 8.52,60.47 U1.E25
M0_DATA17: length 13.4
  TOP w0.14: U1AM1.C8 4.51,69.96 4.1,69.55 3.49,69.55 2.93,68.99 2.93,61.47 5.31,59.1 U1.A23
M0_DATA18: length 14.1
  TOP w0.112: 6.81,60.64 6.81,59.42 U1.C23
  TOP w0.14: U1AM1.A7 5.31,66.95 3.87,65.51 3.87,63.53 3.97,63.43 4.38,63.43 4.48,63.33 4.48,63.19 4.38,63.08 3.97,63.08 3.87,62.98 3.87,62.84 3.97,62.74 4.38,62.74 4.48,62.64 4.48,62.5 4.38,62.4 3.97,62.4 3.87,62.3 3.87,62.06 4.37,61.56 5.88,61.56 6.81,60.64
M0_DATA19: length 13.7
  TOP w0.14: U1AM1.C2 8.99,69.64 8.9,69.55 8.9,65.12 8.76,64.98 6.82,64.98 6.61,64.78 6.61,63.99 6.79,63.81 8.19,63.81 8.9,63.1 8.9,60.62 U1.F25
M0_DATA20: length 13.8
  TOP w0.112: U1.B24 6.16,60.07 6.16,60.69
  TOP w0.14: 6.16,60.69 5.6,61.24 4.2,61.24 3.57,61.88 3.57,65.64 4.91,66.98 4.91,70.37 5.31,70.76 U1AM1.D7
M0_DATA21: length 13.6
  TOP w0.14: U1.D24 8.11,60.08 8.11,61.4 6,63.51 6,65.03 6.56,65.59 7.97,65.59 8.11,65.73 8.11,68.03 7.5,68.64 7.5,68.96 U1AM1.C3
M0_DATA22: length 13.4
  TOP w0.112: 5.44,59.42 6.16,59.42 U1.B23
  TOP w0.14: U1AM1.B8 4.51,69.16 4.11,68.76 4.11,68.24 3.49,67.62 3.24,67.37 3.24,67.15 3.33,67.06 3.52,67.06 3.62,66.97 3.62,66.84 3.52,66.74 3.33,66.74 3.24,66.65 3.24,66.52 3.33,66.43 3.52,66.43 3.62,66.34 3.62,66.21 3.52,66.11 3.33,66.11 3.24,66.02 3.24,61.63 5.44,59.42
M0_DATA23: length 13.3
  TOP w0.14: U1.F24 9.46,60.08 9.46,60.74 9.31,60.89 9.31,63.97 9.17,64.11 7.07,64.11 6.92,64.27 6.92,64.53 7.06,64.67 9.17,64.67 9.31,64.81 9.31,68.05 U1AM1.A2
M0_DATA24: length 22.4
  TOP w0.102: U1.F20 v1(8.8,57.43)
  TOP w0.14: U1AM1.H8 4.51,73.96 4.1,74.36 3.43,74.36 v1(2.94,73.88)
  IN2 w0.102: v1(2.94,73.88) 3.36,73.46 3.36,69.83 3.83,69.36 3.83,68.65 6.94,65.54 6.94,65.06 7.03,64.97 7.24,64.97 7.33,64.88 7.33,64.76 7.24,64.67 7.03,64.67 6.94,64.58 6.94,64.45 7.03,64.36 7.24,64.36 7.33,64.27 7.33,64.15 7.24,64.06 7.03,64.06 6.94,63.97 6.94,61.08 8.44,59.58 8.44,59.58 8.46,59.56 8.46,57.77 v1(8.8,57.43)
M0_DATA25: length 23.3
  TOP w0.102: U1.F21 v1(8.8,58.13)
  TOP w0.14: U1AM1.H7 v1(4.91,73.56)
  IN2 w0.102: v1(4.91,73.56) 4.5,73.16 3.91,73.16 3.69,72.94 3.69,69.96 4.14,69.51 4.14,68.8 7.65,65.29 7.65,62.74 7.74,62.65 8.15,62.65 8.24,62.56 8.24,62.43 8.15,62.34 7.51,62.34 7.42,62.25 7.42,62.13 7.51,62.04 8.15,62.04 8.24,61.95 8.24,61.82 8.15,61.73 7.51,61.73 7.42,61.64 7.42,61.52 7.51,61.43 8.15,61.43 8.24,61.34 8.24,61.21 8.15,61.12 7.74,61.12 7.65,61.03 7.65,60.9 8.47,60.08 8.47,59.94 8.8,59.61 v1(8.8,58.13)
M0_DATA26: length 21
  TOP w0.102: U1.G20 v1(9.45,57.47)
  TOP w0.14: U1AM1.F7 5.31,72.36 v1(4.91,72.76)
  IN2 w0.089: v1(9.45,57.47) 9.13,57.8 9.13,58.4
  IN2 w0.102: v1(4.91,72.76) 4.51,72.36 4.51,68.89 8.49,64.9 8.49,64.62 8.4,64.53 8.07,64.53 7.99,64.44 7.99,64.32 8.07,64.23 8.4,64.23 8.49,64.14 8.49,64.01 8.4,63.92 8.07,63.92 7.99,63.83 7.99,63.71 8.07,63.62 8.4,63.62 8.49,63.53 8.49,63.4 8.4,63.31 8.07,63.31 7.99,63.22 7.99,63.1 8.07,63.01 8.4,63.01 8.49,62.92 8.49,61.22 9.13,60.58 9.13,60.21 9.13,60.21 9.13,59.94 9.13,59.93 9.13,58.4
M0_DATA27: length 20.4
  TOP w0.102: U1.H23 v1(10.77,59.42)
  TOP w0.14: v1(7.53,72.53) 7.53,72.98 U1AM1.H3
  IN2 w0.102: v1(7.53,72.53) 7.53,71.86 7.35,71.68 7.35,71.18 8.57,69.96 8.57,69.67 8.66,69.58 9.04,69.58 9.13,69.49 9.13,69.36 9.04,69.27 8.66,69.27 8.57,69.19 8.57,68.28 9.77,67.08 9.9,67.08 10.35,67.52 10.47,67.52 10.56,67.43 10.56,67.31 10.32,67.06 10.32,66.94 10.41,66.85 10.53,66.85 10.78,67.09 10.9,67.09 10.99,67 10.99,66.88 10.7,66.58 10.7,66.46 11.36,65.79 11.36,60.94 10.77,60.34 v1(10.77,59.42)
M0_DATA28: length 23.9
  TOP w0.102: U1.G21 v1(9.45,58.13)
  TOP w0.14: U1AM1.F8 v1(4.91,71.96)
  IN2 w0.102: v1(9.45,58.13) 9.45,60.88 9.31,61.02 9.31,61.41 9.22,61.5 8.89,61.5 8.8,61.59 8.8,61.72 8.89,61.81 9.22,61.81 9.31,61.9 9.31,62.02 9.22,62.11 8.89,62.11 8.8,62.2 8.8,62.33 8.89,62.42 9.22,62.42 9.31,62.51 9.31,62.63 9.22,62.72 8.89,62.72 8.8,62.81 8.8,62.94 8.89,63.03 9.22,63.03 9.31,63.12 9.31,63.24 9.22,63.33 8.89,63.33 8.8,63.42 8.8,63.55 8.89,63.64 9.22,63.64 9.31,63.73 9.31,63.85 9.22,63.94 8.89,63.94 8.8,64.03 8.8,64.16 8.89,64.25 9.22,64.25 9.31,64.34 9.31,64.56 8.75,65.12 8.75,65.24 9.02,65.52 9.02,65.64 8.93,65.73 8.81,65.73 8.53,65.46 8.41,65.46 8.32,65.55 8.32,65.67 8.59,65.95 8.59,66.07 8.5,66.16 8.38,66.16 8.1,65.89 7.98,65.89 7.89,65.98 7.89,66.1 8.16,66.38 8.16,66.5 8.07,66.59 7.95,66.59 7.67,66.32 7.55,66.32 4.95,68.92 4.95,70.5 5.32,70.87 5.32,71.55 v1(4.91,71.96)
M0_DATA29: length 20.2
  TOP w0.102: U1.J21 v1(10.77,57.47)
  TOP w0.14: v1(8.9,71.2) 8.9,71.95 U1AM1.F2
  IN2 w0.102: v1(8.9,71.2) 10.72,69.38 10.85,69.38 11.29,69.82 11.42,69.82 11.51,69.73 11.51,69.61 11.06,69.16 11.06,69.04 11.15,68.95 11.28,68.95 11.73,69.39 11.85,69.39 11.94,69.3 11.94,69.18 11.5,68.73 11.5,68.61 12.08,68.03 12.08,58.77 v1(10.77,57.47)
M0_DATA30: length 19.6
  TOP w0.102: U1.J20 v1(11.43,56.82)
  TOP w0.14: v1(10.85,72.1) 10.47,72.47 10.47,73.34 10.25,73.56 9.71,73.56 U1AM1.G2
  IN2 w0.102: v1(10.85,72.1) 11.19,71.76 11.19,70.59 12.44,69.33 12.44,57.84 v1(11.43,56.82)
M0_DATA31: length 20.8
  TOP w0.102: U1.H22 v1(10.76,58.77)
  TOP w0.14: U1AM1.E3 8.51,71.52 v1(8.09,71.1)
  IN2 w0.102: v1(8.09,71.1) 10.09,69.09 10.09,68.76 10,68.67 9.09,68.67 9,68.58 9,68.46 9.09,68.37 10,68.37 10.09,68.28 10.09,68.12 10.29,67.92 10.51,67.92 11.03,68.44 11.15,68.44 11.24,68.35 11.24,68.22 10.87,67.86 10.87,67.73 10.96,67.64 11.09,67.64 11.46,68.01 11.58,68.01 11.67,67.92 11.67,67.79 11.31,67.42 11.31,67.3 11.69,66.91 11.69,66.72 11.61,66.63 11.28,66.63 11.19,66.54 11.19,66.42 11.28,66.33 11.61,66.33 11.69,66.24 11.69,60.85 11.1,60.25 11.1,59.11 v1(10.76,58.77)
M0_DATA32: length 13.4
  TOP w0.102: U1.AD24 21.21,59.75 21.54,60.08 21.81,60.08 22.03,60.3 22.03,60.69
  TOP w0.14: U1AM3.A3 23.75,67.54 23.75,67.18 24.52,66.4 24.52,66.17 24.42,66.07 24.16,66.07 24.06,65.97 24.06,65.83 24.16,65.73 24.42,65.73 24.52,65.63 24.52,65.49 24.42,65.39 24.16,65.39 24.06,65.28 24.06,65.14 24.16,65.04 24.42,65.04 24.52,64.94 24.52,64.8 24.42,64.7 24.16,64.7 24.06,64.6 24.06,64.46 24.16,64.36 24.42,64.36 24.52,64.26 24.52,63.89 23.61,62.97 22.41,62.97 22.03,62.59 22.03,60.69
M0_DATA33: length 14.6
  TOP w0.14: U1AM3.A7 20.89,68.36 21.03,68.22 21.03,65.62 20.89,65.48 19.69,65.48 19.59,65.38 19.59,65.24 19.69,65.14 21.16,65.14 21.26,65.04 21.26,64.89 21.16,64.79 19.69,64.79 19.59,64.69 19.59,64.55 19.69,64.45 20.85,64.45 20.95,64.35 20.95,64.18 19.64,62.87 19.64,60.48 U1.AB25
M0_DATA34: length 13.8
  TOP w0.14: U1AM3.B8 19.51,69.16 19.36,69.02 19.36,68.26 18.74,67.64 18.74,67.45 18.85,67.34 19.83,67.34 19.95,67.22 19.95,66.98 19.85,66.88 19.67,66.88 19.57,66.78 19.57,66.64 19.67,66.54 19.85,66.54 19.95,66.44 19.95,66.25 19.85,66.15 18.84,66.15 18.72,66.02 18.72,65.86 18.91,65.67 18.91,65.52 18.72,65.33 18.72,65.17 18.91,64.98 18.91,64.83 18.72,64.64 18.72,64.33 18.86,64.19 19.09,64.19 19.37,63.91 19.37,63.51 18.72,62.86 18.72,60.09 U1.Y24
M0_DATA35: length 12.9
  TOP w0.102: U1.AE23 22.15,59.1 23.35,60.3 23.35,60.76
  TOP w0.14: U1AM3.A2 24.55,67.54 24.55,67.32 25.18,66.68 25.18,62.16 25.08,62.06 24.75,62.06 24.65,61.96 24.65,61.82 24.75,61.71 25.08,61.71 25.18,61.61 25.18,61.35 25.04,61.2 23.57,61.2 23.35,60.98 23.35,60.76
M0_DATA36: length 14.4
  TOP w0.14: U1AM3.D7 20.15,70.37 20.15,67.98 20.25,67.88 20.61,67.88 20.71,67.78 20.71,67.48 20.61,67.38 20.43,67.38 20.33,67.28 20.33,67.14 20.43,67.04 20.61,67.04 20.71,66.94 20.71,66.79 20.61,66.69 20.43,66.69 20.33,66.59 20.33,66.45 20.43,66.35 20.61,66.35 20.71,66.25 20.71,65.92 20.61,65.82 19.39,65.82 19.25,65.68 19.25,64.45 19.59,64.11 20,64.11 20.13,63.99 20.13,63.79 19.05,62.71 U1.AA25
M0_DATA37: length 14.1
  TOP w0.102: 21.63,60.84 21.35,60.56 21.35,60.24 21.18,60.08 20.89,60.08 20.67,59.86 20.67,59.4 U1.AC23
  TOP w0.14: 21.63,60.84 21.63,62.69 22.26,63.33 23.45,63.33 23.73,63.61 23.73,66.76 23.33,67.16 23.33,68.03 22.95,68.41 22.95,69.36 23.14,69.55 23.61,69.55 23.75,69.69 U1AM3.C3
M0_DATA38: length 13.6
  TOP w0.102: U1.AD23 21.35,59.42 22.09,59.42 22.99,60.32 22.99,60.8
  TOP w0.14: U1AM3.C2 24.14,69.56 24.14,67.21 24.83,66.53 24.83,62.62 23.79,61.58 23.4,61.58 22.99,61.17 22.99,60.8
M0_DATA39: length 15.7
  TOP w0.14: U1AM3.C8 19.75,69.66 19.61,69.52 18.7,69.52 18.57,69.65 18.57,70.23 18.47,70.34 18.27,70.34 18.17,70.24 18.17,68.38 18.38,68.17 18.38,66.98 18.48,66.88 19.06,66.88 19.16,66.78 19.16,66.64 19.06,66.54 18.48,66.54 18.38,66.44 18.38,63.98 18.48,63.88 18.93,63.88 19.03,63.78 19.03,63.63 18.93,63.53 18.48,63.53 18.38,63.43 18.38,61.18 18.28,61.08 17.99,61.08 17.89,60.98 17.89,60.84 17.99,60.74 18.28,60.74 18.38,60.64 U1.Y25
M0_DATA40: length 17.2
  TOP w0.102: U1.V23 17.9,59.93 v1(17.9,60.29)
  BOTTOM w0.14: U1AM4.D7 24.17,70.34 24.17,66.26 22.61,64.71 22.17,64.71 22.01,64.55 21.87,64.55 21.66,64.77 21.52,64.77 21.41,64.67 21.41,64.52 21.63,64.31 21.63,64.17 21.53,64.07 21.39,64.07 21.02,64.43 20.88,64.43 20.78,64.33 20.78,64.19 21.14,63.82 21.14,63.68 20.1,62.64 20.1,62.2 18.2,60.29 v1(17.9,60.29)
M0_DATA41: length 16.4
  TOP w0.102: v1(16.08,60.91) 16.08,60.28 16.07,60.09 U1.T24
  BOTTOM w0.14: U1AM4.C3 20.55,69.96 21.4,69.11 21.4,67.8 19.49,65.89 19.35,65.89 19.1,66.14 18.96,66.14 18.85,66.04 18.85,65.9 19.11,65.65 19.11,65.51 19.01,65.41 18.86,65.41 18.61,65.66 18.47,65.66 18.37,65.56 18.37,65.42 18.62,65.16 18.62,65.02 18.52,64.92 18.38,64.92 18.13,65.17 17.99,65.17 17.88,65.07 17.88,64.93 18.14,64.68 18.14,64.54 18.04,64.44 17.89,64.44 17.64,64.69 17.5,64.69 17.4,64.59 17.4,64.45 17.65,64.19 17.65,64.05 16.46,62.86 16.46,61.3 v1(16.08,60.91)
M0_DATA42: length 16
  TOP w0.102: U1.W22 v1(18.06,58.77)
  BOTTOM w0.14: v1(18.06,58.77) 18.88,59.6 18.88,60.08 26.17,67.37 26.17,68.92 25.54,69.55 24.96,69.55 24.96,69.55 U1AM4.C8
M0_DATA43: length 16.4
  TOP w0.102: U1.W23 v1(18.06,59.42)
  BOTTOM w0.14: U1AM4.B8 24.55,69.16 24.93,68.78 24.93,68.25 25.26,67.92 25.62,67.92 25.82,67.73 25.82,67.48 25.7,67.37 25.56,67.37 25.48,67.45 25.34,67.45 25.24,67.35 25.24,67.21 25.32,67.13 25.32,66.98 25.22,66.88 25.07,66.88 24.75,67.2 24.61,67.2 24.51,67.1 24.51,66.96 24.83,66.64 24.83,66.49 22.56,64.22 22.11,64.22 21.92,64.03 21.92,63.63 21.75,63.46 21.35,63.46 21.18,63.29 21.18,62.88 21.01,62.71 20.6,62.71 20.46,62.57 20.46,62.13 18.53,60.19 18.53,59.9 v1(18.06,59.42)
M0_DATA44: length 18.2
  TOP w0.102: U1.R23 v1(15.4,59.43)
  BOTTOM w0.14: U1AM4.A2 19.75,67.52 19.44,67.21 18.42,67.21 18.42,67.2 18.27,67.2 17.96,67.52 17.82,67.52 17.72,67.42 17.72,67.28 18.03,66.96 18.03,66.82 17.93,66.72 17.79,66.72 17.47,67.03 17.33,67.03 17.23,66.93 17.23,66.79 17.55,66.48 17.55,66.33 17.38,66.17 15.95,66.17 15.85,66.27 15.85,67.14 15.75,67.24 15.6,67.24 15.5,67.14 15.5,66.27 15.4,66.17 15.1,66.17 14.13,65.21 14.13,63.89 15.4,62.62 15.4,59.43 v1(15.4,59.43)
